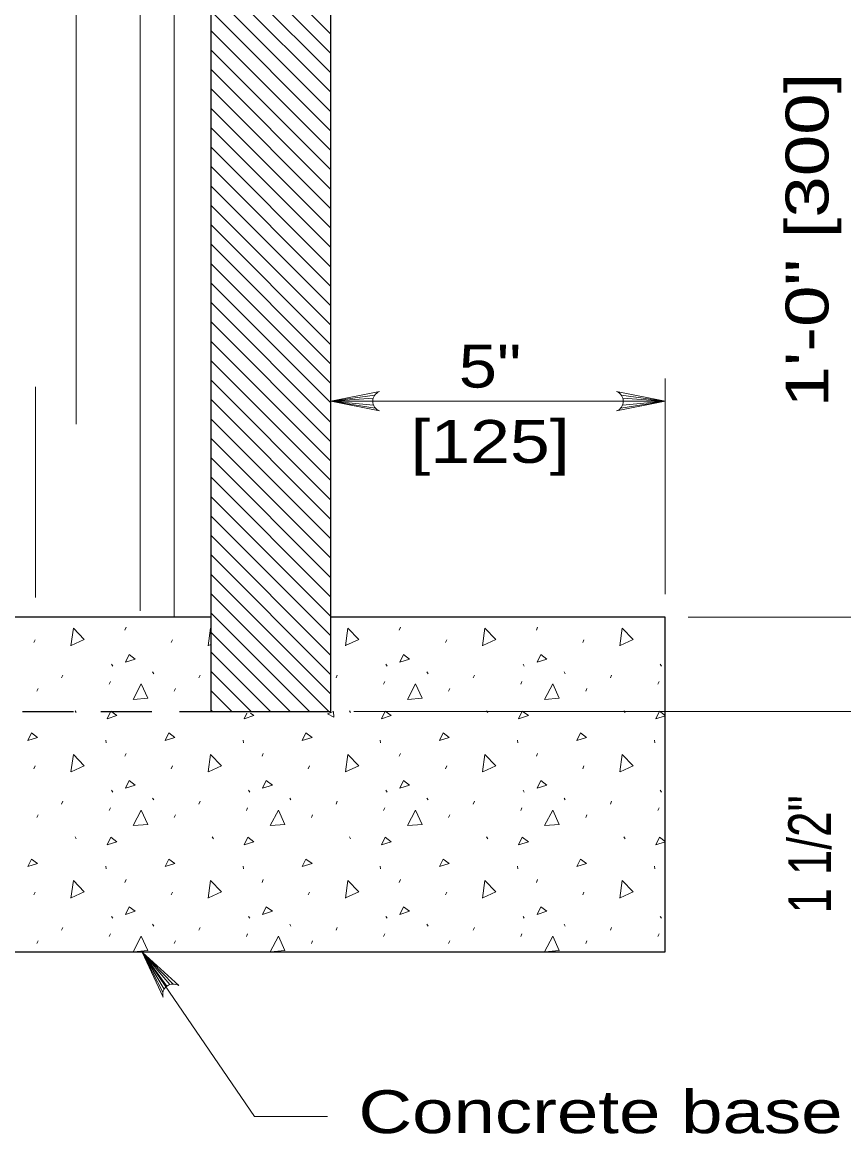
# Model space of a CAD drawing. Extents: x 1302.9 to 1336.9, y 688.5 to 710.5.
# Drawn here: x 1311.457 to 1314.45, y 691.328 to 695.374 of the extents above; entities that cross this region are included whole.
import ezdxf
from ezdxf.enums import TextEntityAlignment as Align

# ---------------------------------------------------------------- set-up
doc = ezdxf.new("R2010")
doc.units = 0
doc.header["$LTSCALE"] = 0.062
doc.linetypes.add('MEDIUM_DASHED', pattern=[4.5, 3, -1.5])
doc.layers.add('1', color=7, linetype='Continuous', lineweight=13)

msp = doc.modelspace()

# ---------------------------------------------------------------- linework, layer by layer
at = {"layer": '1', "lineweight": 25}
for p, q in [((1312.58092, 692.86483), (1312.58092, 698.95525)), ((1312.14367, 693.20833), (1307.73933, 693.20833))]:
    msp.add_line(p, q, dxfattribs=at)
at = {"layer": '1'}
for p, q in [((1312.00975, 693.20825), (1312.00975, 696.27125)), ((1311.65292, 696.03525), (1311.65292, 693.91133)), ((1311.88633, 693.23183), (1311.88633, 696.02642)), ((1312.58092, 695.331), (1312.14367, 695.76825)), ((1312.58092, 695.26033), (1312.14367, 695.69758)), ((1312.58092, 695.18967), (1312.14367, 695.62692)), ((1312.58092, 695.119), (1312.14367, 695.55625)), ((1312.58092, 695.04833), (1312.14367, 695.48558)), ((1312.58092, 694.97767), (1312.14367, 695.41492)), ((1312.58092, 694.907), (1312.14367, 695.34425)), ((1312.58092, 694.83633), (1312.14367, 695.27358)), ((1312.58092, 694.76567), (1312.14367, 695.20283)), ((1312.58092, 694.695), (1312.14367, 695.13225)), ((1312.58092, 694.62433), (1312.14367, 695.0615)), ((1312.58092, 694.55367), (1312.14367, 694.99092)), ((1312.58092, 694.48292), (1312.14367, 694.92017)), ((1312.58092, 694.41233), (1312.14367, 694.84958)), ((1312.58092, 694.34158), (1312.14367, 694.77883)), ((1312.58092, 694.27092), (1312.14367, 694.70817)), ((1312.58092, 694.20025), (1312.14367, 694.6375)), ((1312.58092, 694.12958), (1312.14367, 694.56683)), ((1312.58092, 694.05892), (1312.14367, 694.49617)), ((1312.58092, 693.98825), (1312.14367, 694.4255)), ((1312.58092, 693.91758), (1312.14367, 694.35483)), ((1312.58092, 693.84692), (1312.14367, 694.28417)), ((1312.58092, 693.77625), (1312.14367, 694.2135)), ((1312.58092, 693.70558), (1312.14367, 694.14283)), ((1311.50533, 693.28042), (1311.50533, 694.0475)), ((1312.58092, 693.63492), (1312.14367, 694.07217)), ((1313.79908, 693.29167), (1313.79908, 694.07775)), ((1312.58092, 693.56425), (1312.14367, 694.0015)), ((1312.74117, 694.01692), (1312.58092, 693.9945)), ((1312.73575, 694.00583), (1312.58092, 693.9945)), ((1313.63883, 694.01692), (1313.79908, 693.9945)), ((1313.64425, 694.00583), (1313.79908, 693.9945)), ((1312.58092, 693.9945), (1313.79908, 693.9945)), ((1312.73408, 693.9945), (1312.58092, 693.9945)), ((1312.73692, 693.98008), (1312.58092, 693.9945)), ((1312.74308, 693.96967), (1312.58092, 693.9945)), ((1313.637, 693.96967), (1313.79908, 693.9945)), ((1313.64308, 693.98008), (1313.79908, 693.9945)), ((1313.64592, 693.9945), (1313.79908, 693.9945)), ((1312.58092, 693.49358), (1312.14367, 693.93083)), ((1312.58092, 693.42292), (1312.14367, 693.86017)), ((1312.58092, 693.35225), (1312.14367, 693.7895)), ((1312.58092, 693.28158), (1312.14367, 693.71883)), ((1312.58092, 693.21092), (1312.14367, 693.64817)), ((1312.58092, 693.14025), (1312.14367, 693.5775)), ((1312.58092, 693.0695), (1312.14367, 693.50675)), ((1312.58092, 692.99892), (1312.14367, 693.43617)), ((1312.58092, 692.92817), (1312.14367, 693.36542)), ((1312.57367, 692.86483), (1312.14367, 693.29483)), ((1312.503, 692.86483), (1312.14367, 693.22408)), ((1313.88233, 693.20833), (1315.504, 693.20833)), ((1311.83058, 693.16158), (1311.835, 693.17158)), ((1312.43233, 692.86483), (1312.14367, 693.1535)), ((1312.83017, 693.16158), (1312.83458, 693.17158)), ((1313.32992, 693.16158), (1313.33433, 693.17158)), ((1311.49942, 693.11608), (1311.50392, 693.12608)), ((1311.99917, 693.11608), (1312.00367, 693.12608)), ((1312.14367, 693.10892), (1312.13525, 693.105)), ((1312.99875, 693.11608), (1313.00325, 693.12608)), ((1313.4985, 693.11608), (1313.503, 693.12608)), ((1312.36158, 692.86483), (1312.14367, 693.08275)), ((1311.78192, 693.03733), (1311.78642, 693.03075)), ((1312.78142, 693.03733), (1312.78592, 693.03075)), ((1313.28117, 693.03733), (1313.28567, 693.03075)), ((1313.78092, 693.03733), (1313.78542, 693.03075)), ((1311.6005, 692.98742), (1311.60492, 692.99742)), ((1311.93142, 693.00917), (1311.93583, 693.0025)), ((1312.10025, 692.98742), (1312.10467, 692.99742)), ((1312.291, 692.86483), (1312.14367, 693.01217)), ((1312.6, 692.98742), (1312.60442, 692.99742)), ((1312.93092, 693.00917), (1312.93533, 693.0025)), ((1313.09975, 692.98742), (1313.10417, 692.99742)), ((1313.43067, 693.00917), (1313.43508, 693.0025)), ((1313.5995, 692.98742), (1313.60392, 692.99742)), ((1311.51058, 692.93875), (1311.515, 692.94867)), ((1311.77358, 692.96425), (1311.778, 692.97425)), ((1312.01033, 692.93875), (1312.01475, 692.94867)), ((1312.77308, 692.96425), (1312.7775, 692.97425)), ((1313.00992, 692.93875), (1313.01433, 692.94867)), ((1313.27283, 692.96425), (1313.27725, 692.97425)), ((1313.50967, 692.93875), (1313.51408, 692.94867)), ((1313.77258, 692.96425), (1313.777, 692.97425)), ((1312.22025, 692.86483), (1312.14367, 692.94142)), ((1311.64925, 692.86775), (1311.65367, 692.86108)), ((1312.14967, 692.86483), (1312.14367, 692.87083)), ((1312.64883, 692.86775), (1312.65325, 692.86108)), ((1316.72208, 692.86483), (1312.66425, 692.86483)), ((1313.14858, 692.86775), (1313.153, 692.86108)), ((1313.64833, 692.86775), (1313.65275, 692.86108)), ((1312.2655, 692.83892), (1312.27542, 692.85958)), ((1313.799, 692.84958), (1313.76475, 692.83892)), ((1311.76142, 692.76125), (1311.76258, 692.75125)), ((1312.26117, 692.76125), (1312.26233, 692.75125)), ((1312.76092, 692.76125), (1312.76208, 692.75125)), ((1313.26067, 692.76125), (1313.26183, 692.75125)), ((1313.76042, 692.76125), (1313.76158, 692.75125)), ((1311.83058, 692.70242), (1311.835, 692.71242)), ((1312.33042, 692.70242), (1312.33475, 692.71242)), ((1312.83017, 692.70242), (1312.83458, 692.71242)), ((1313.32992, 692.70242), (1313.33433, 692.71242)), ((1311.49942, 692.65692), (1311.50392, 692.66692)), ((1311.99917, 692.65692), (1312.00367, 692.66692)), ((1312.499, 692.65692), (1312.5035, 692.66692)), ((1312.99875, 692.65692), (1313.00325, 692.66692)), ((1313.4985, 692.65692), (1313.503, 692.66692)), ((1311.78192, 692.57825), (1311.78642, 692.57158)), ((1311.93142, 692.55), (1311.93583, 692.54333)), ((1312.28167, 692.57825), (1312.28617, 692.57158)), ((1312.43117, 692.55), (1312.43558, 692.54333)), ((1312.78142, 692.57825), (1312.78592, 692.57158)), ((1312.93092, 692.55), (1312.93533, 692.54333)), ((1313.28117, 692.57825), (1313.28567, 692.57158)), ((1313.43067, 692.55), (1313.43508, 692.54333)), ((1313.78092, 692.57825), (1313.78542, 692.57158)), ((1311.6005, 692.52825), (1311.60492, 692.53825)), ((1311.77358, 692.50508), (1311.778, 692.51508)), ((1312.10025, 692.52825), (1312.10467, 692.53825)), ((1312.27333, 692.50508), (1312.27775, 692.51508)), ((1312.6, 692.52825), (1312.60442, 692.53825)), ((1312.77308, 692.50508), (1312.7775, 692.51508)), ((1313.09975, 692.52825), (1313.10417, 692.53825)), ((1313.27283, 692.50508), (1313.27725, 692.51508)), ((1313.5995, 692.52825), (1313.60392, 692.53825)), ((1313.77258, 692.50508), (1313.777, 692.51508)), ((1311.51058, 692.47958), (1311.515, 692.4895)), ((1312.01033, 692.47958), (1312.01475, 692.4895)), ((1312.51008, 692.47958), (1312.5145, 692.4895)), ((1313.00992, 692.47958), (1313.01433, 692.4895)), ((1313.50967, 692.47958), (1313.51408, 692.4895)), ((1311.64925, 692.40858), (1311.65367, 692.40192)), ((1312.14908, 692.40858), (1312.15342, 692.40192)), ((1312.64883, 692.40858), (1312.65325, 692.40192)), ((1313.14858, 692.40858), (1313.153, 692.40192)), ((1313.64833, 692.40858), (1313.65275, 692.40192)), ((1313.799, 692.39042), (1313.76475, 692.37975)), ((1311.76142, 692.30217), (1311.76258, 692.29217)), ((1312.26117, 692.30217), (1312.26233, 692.29217)), ((1312.76092, 692.30217), (1312.76208, 692.29217)), ((1313.26067, 692.30217), (1313.26183, 692.29217)), ((1313.76042, 692.30217), (1313.76158, 692.29217)), ((1311.83058, 692.24325), (1311.835, 692.25325)), ((1312.33042, 692.24325), (1312.33475, 692.25325)), ((1312.83017, 692.24325), (1312.83458, 692.25325)), ((1313.32992, 692.24325), (1313.33433, 692.25325)), ((1311.49942, 692.19775), (1311.50392, 692.20775)), ((1311.99917, 692.19775), (1312.00367, 692.20775)), ((1312.499, 692.19775), (1312.5035, 692.20775)), ((1312.99875, 692.19775), (1313.00325, 692.20775)), ((1313.4985, 692.19775), (1313.503, 692.20775)), ((1311.78192, 692.11908), (1311.78642, 692.11242)), ((1312.28167, 692.11908), (1312.28617, 692.11242)), ((1312.78142, 692.11908), (1312.78592, 692.11242)), ((1313.28117, 692.11908), (1313.28567, 692.11242)), ((1313.78092, 692.11908), (1313.78542, 692.11242)), ((1311.6005, 692.06908), (1311.60492, 692.07908)), ((1311.77358, 692.04592), (1311.778, 692.05592)), ((1311.93142, 692.09083), (1311.93583, 692.08417)), ((1312.10025, 692.06908), (1312.10467, 692.07908)), ((1312.27333, 692.04592), (1312.27775, 692.05592)), ((1312.43117, 692.09083), (1312.43558, 692.08417)), ((1312.6, 692.06908), (1312.60442, 692.07908)), ((1312.77308, 692.04592), (1312.7775, 692.05592)), ((1312.93092, 692.09083), (1312.93533, 692.08417)), ((1313.09975, 692.06908), (1313.10417, 692.07908)), ((1313.27283, 692.04592), (1313.27725, 692.05592)), ((1313.43067, 692.09083), (1313.43508, 692.08417)), ((1313.5995, 692.06908), (1313.60392, 692.07908)), ((1313.77258, 692.04592), (1313.777, 692.05592)), ((1311.51058, 692.02042), (1311.515, 692.03033)), ((1312.01033, 692.02042), (1312.01475, 692.03033)), ((1312.51008, 692.02042), (1312.5145, 692.03033)), ((1313.00992, 692.02042), (1313.01433, 692.03033)), ((1313.50967, 692.02042), (1313.51408, 692.03033)), ((1311.98417, 691.86567), (1311.89392, 691.98942)), ((1311.97425, 691.85483), (1311.89392, 691.98942)), ((1311.9695, 691.84375), (1311.89392, 691.98942)), ((1311.99433, 691.871), (1311.89392, 691.98942)), ((1312.0065, 691.87317), (1311.89392, 691.98942))]:
    msp.add_line(p, q, dxfattribs=at)
at = {"layer": '1', "linetype": 'MEDIUM_DASHED', "lineweight": 25}
msp.add_line((1307.73933, 692.86483), (1312.14367, 692.86483), dxfattribs=at)
at = {"layer": '1', "lineweight": 25}
for points in [[(1312.92967, 700.76658), (1312.73708, 700.04825), (1312.58092, 700.04825), (1312.14367, 700.04825), (1312.14367, 692.86483), (1312.58092, 692.86483)], [(1306.08392, 691.99033), (1313.799, 691.99033), (1313.799, 693.20833), (1312.58092, 693.20833)]]:
    msp.add_lwpolyline(points, dxfattribs=at)
at = {"layer": '1'}
for points in [[(1312.75792, 693.95908), (1312.58092, 693.9945), (1312.75792, 694.02992)], [(1313.62208, 693.95908), (1313.79908, 693.9945), (1313.62208, 694.02992)], [(1311.63442, 693.10458), (1311.64325, 693.16808), (1311.683, 693.127), (1311.63542, 693.105)], [(1312.13425, 693.10458), (1312.14308, 693.16808), (1312.14367, 693.1675)], [(1312.634, 693.10458), (1312.64283, 693.16808), (1312.68258, 693.127), (1312.635, 693.105)], [(1313.13375, 693.10458), (1313.14258, 693.16808), (1313.18233, 693.127), (1313.13475, 693.105)], [(1313.6335, 693.10458), (1313.64233, 693.16808), (1313.68208, 693.127), (1313.6345, 693.105)], [(1311.8605, 692.90875), (1311.8905, 692.96533), (1311.91383, 692.91317), (1311.86167, 692.90875)], [(1312.86008, 692.90875), (1312.89, 692.96533), (1312.91333, 692.91317), (1312.86125, 692.90875)], [(1313.35983, 692.90875), (1313.38975, 692.96533), (1313.41308, 692.91317), (1313.361, 692.90875)], [(1312.592, 692.84442), (1312.56942, 692.85642), (1312.59025, 692.86575), (1312.592, 692.84492)], [(1313.76475, 692.83892), (1313.77808, 692.86667), (1313.799, 692.851)], [(1312.28825, 692.85958), (1312.30108, 692.85), (1312.2655, 692.83892)], [(1311.63442, 692.64542), (1311.64325, 692.70892), (1311.683, 692.66783), (1311.63542, 692.64583)], [(1312.13425, 692.64542), (1312.14308, 692.70892), (1312.18275, 692.66783), (1312.13525, 692.64583)], [(1312.634, 692.64542), (1312.64283, 692.70892), (1312.68258, 692.66783), (1312.635, 692.64583)], [(1313.13375, 692.64542), (1313.14258, 692.70892), (1313.18233, 692.66783), (1313.13475, 692.64583)], [(1313.6335, 692.64542), (1313.64233, 692.70892), (1313.68208, 692.66783), (1313.6345, 692.64583)], [(1311.8605, 692.44967), (1311.8905, 692.50617), (1311.91383, 692.454), (1311.86167, 692.44967)], [(1312.36025, 692.44967), (1312.39025, 692.50617), (1312.41358, 692.454), (1312.36142, 692.44967)], [(1312.86008, 692.44967), (1312.89, 692.50617), (1312.91333, 692.454), (1312.86125, 692.44967)], [(1313.35983, 692.44967), (1313.38975, 692.50617), (1313.41308, 692.454), (1313.361, 692.44967)], [(1313.76475, 692.37975), (1313.77808, 692.4075), (1313.799, 692.39183)], [(1311.63442, 692.18625), (1311.64325, 692.24975), (1311.683, 692.20867), (1311.63542, 692.18667)], [(1312.13425, 692.18625), (1312.14308, 692.24975), (1312.18275, 692.20867), (1312.13525, 692.18667)], [(1312.634, 692.18625), (1312.64283, 692.24975), (1312.68258, 692.20867), (1312.635, 692.18667)], [(1313.13375, 692.18625), (1313.14258, 692.24975), (1313.18233, 692.20867), (1313.13475, 692.18667)], [(1313.6335, 692.18625), (1313.64233, 692.24975), (1313.68208, 692.20867), (1313.6345, 692.18667)], [(1311.8605, 691.9905), (1311.8905, 692.047), (1311.91383, 691.99492), (1311.86167, 691.9905)], [(1312.36025, 691.9905), (1312.39025, 692.047), (1312.41358, 691.99492), (1312.36142, 691.9905)], [(1313.35983, 691.9905), (1313.38975, 692.047), (1313.41308, 691.99492), (1313.361, 691.9905)], [(1311.96967, 691.8255), (1311.89392, 691.98942), (1312.02683, 691.86725)], [(1311.89392, 691.98942), (1312.3025, 691.39125), (1312.56908, 691.39125)]]:
    msp.add_lwpolyline(points, dxfattribs=at)
for points in [[(1311.83275, 693.04508), (1311.84608, 693.07283), (1311.86833, 693.05617)], [(1312.83233, 693.04508), (1312.84567, 693.07283), (1312.86783, 693.05617)], [(1313.33208, 693.04508), (1313.34542, 693.07283), (1313.36767, 693.05617)], [(1311.76575, 692.83892), (1311.77908, 692.86667), (1311.80125, 692.85)], [(1312.76525, 692.83892), (1312.77858, 692.86667), (1312.80083, 692.85)], [(1313.265, 692.83892), (1313.27833, 692.86667), (1313.30058, 692.85)], [(1311.4775, 692.7595), (1311.49083, 692.78733), (1311.513, 692.77067)], [(1311.97733, 692.7595), (1311.99058, 692.78733), (1312.01275, 692.77067)], [(1312.47708, 692.7595), (1312.49042, 692.78733), (1312.5125, 692.77067)], [(1312.97683, 692.7595), (1312.99017, 692.78733), (1313.01233, 692.77067)], [(1313.47658, 692.7595), (1313.48992, 692.78733), (1313.51208, 692.77067)], [(1311.83275, 692.586), (1311.84608, 692.61367), (1311.86833, 692.597)], [(1312.33258, 692.586), (1312.34583, 692.61367), (1312.36808, 692.597)], [(1312.83233, 692.586), (1312.84567, 692.61367), (1312.86783, 692.597)], [(1313.33208, 692.586), (1313.34542, 692.61367), (1313.36767, 692.597)], [(1311.76575, 692.37975), (1311.77908, 692.4075), (1311.80125, 692.39083)], [(1312.2655, 692.37975), (1312.27883, 692.4075), (1312.30108, 692.39083)], [(1312.76525, 692.37975), (1312.77858, 692.4075), (1312.80083, 692.39083)], [(1313.265, 692.37975), (1313.27833, 692.4075), (1313.30058, 692.39083)], [(1311.4775, 692.3005), (1311.49083, 692.32817), (1311.513, 692.3115)], [(1311.97733, 692.3005), (1311.99058, 692.32817), (1312.01275, 692.3115)], [(1312.47708, 692.3005), (1312.49042, 692.32817), (1312.5125, 692.3115)], [(1312.97683, 692.3005), (1312.99017, 692.32817), (1313.01233, 692.3115)], [(1313.47658, 692.3005), (1313.48992, 692.32817), (1313.51208, 692.3115)], [(1311.83275, 692.12683), (1311.84608, 692.15458), (1311.86833, 692.13792)], [(1312.33258, 692.12683), (1312.34583, 692.15458), (1312.36808, 692.13792)], [(1312.83233, 692.12683), (1312.84567, 692.15458), (1312.86783, 692.13792)], [(1313.33208, 692.12683), (1313.34542, 692.15458), (1313.36767, 692.13792)]]:
    msp.add_lwpolyline(points, close=True, dxfattribs=at)
for centre, start, end in [((1312.77222, 693.99453), 112.08782, 247.91395), ((1313.60781, 693.99453), 292.08605, 67.91218), ((1312.0067, 691.83485), 58.18971, 194.01584)]:
    msp.add_arc(centre, 0.0382, start, end, dxfattribs=at)

# ---------------------------------------------------------------- texts
at = {"layer": '1', "width": 1.3}
msp.add_text('1\'-0" [300]', height=0.156, rotation=90, dxfattribs=at).set_placement((1314.39367, 693.972))
at = {"layer": '1'}
for s, width, p in [('5"', 1.2, (1313.16096, 694.04417)), ('[125]', 1.25, (1313.16092, 693.77017))]:
    msp.add_text(s, height=0.156, dxfattribs=dict(at, width=width)).set_placement(p, align=Align.CENTER)
at = {"layer": '1', "width": 0.8}
msp.add_text('1 1/2"', height=0.156, rotation=90, dxfattribs=at).set_placement((1314.40342, 692.34521), align=Align.CENTER)
at = {"layer": '1', "width": 1.3}
msp.add_text('Concrete base', height=0.156, dxfattribs=at).set_placement((1312.68133, 691.33033))

doc.saveas('drawing.dxf')
